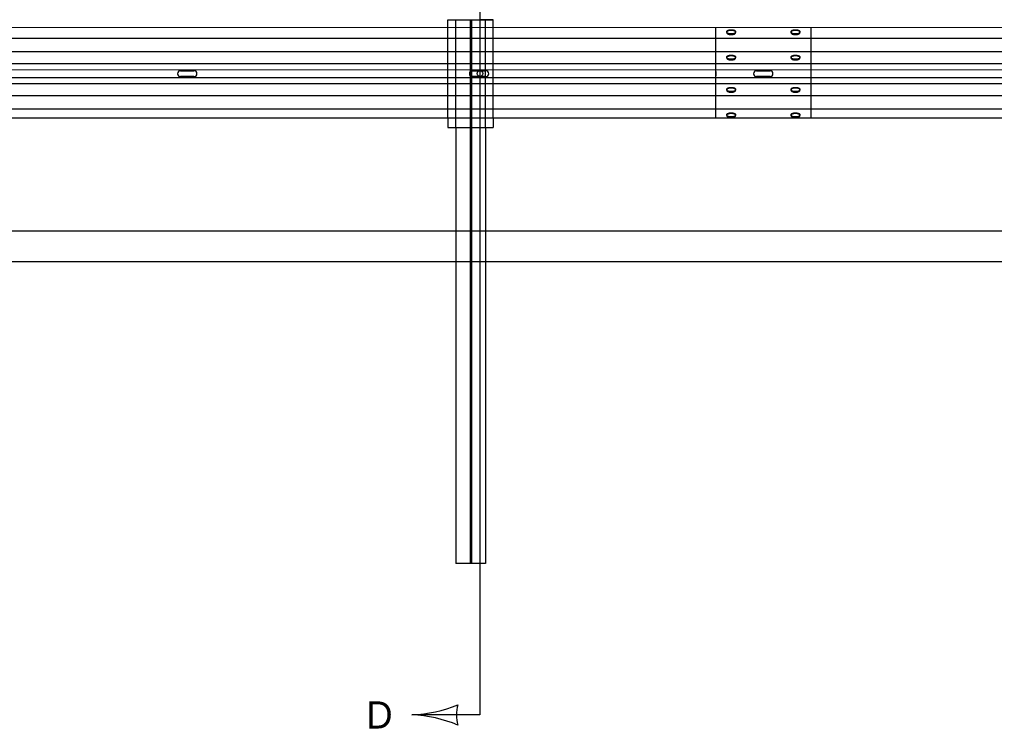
# Model space of a CAD drawing. Extents: x 49991 to 50160, y 49948 to 50051.
# Drawn here: x 50006.556 to 50008.707, y 49993.954 to 49995.519 of the extents above; entities that cross this region are included whole.
import ezdxf

# ---------------------------------------------------------------- set-up
doc = ezdxf.new("R2010")
doc.units = 0
for name, color, linetype in [('Level 1', 7, 'Continuous'), ('Level 2', 7, 'Continuous'), ('Level 3', 7, 'Continuous'), ('Level 4', 7, 'Continuous'), ('Level 6', 7, 'Continuous')]:
    doc.layers.add(name, color=color, linetype=linetype)

msp = doc.modelspace()

# ---------------------------------------------------------------- linework, layer by layer
at = {"layer": 'Level 1'}
for p, q in [((50007.5008, 49995.5184), (50007.6008, 49995.5184)), ((50007.5008, 49995.5018), (50007.5008, 49995.5184)), ((50007.5185, 49995.5184), (50007.5841, 49995.5184)), ((50007.6008, 49995.5184), (50007.5716, 49995.5184)), ((50007.6008, 49995.5018), (50007.6008, 49995.5184)), ((50004.3866, 49995.502), (50011.6716, 49995.5015)), ((50008.0917, 49995.3012), (50008.0917, 49995.5017)), ((50008.1159, 49995.4918), (50008.1159, 49995.4903)), ((50008.1238, 49995.4962), (50008.1277, 49995.4962)), ((50008.1238, 49995.4947), (50008.1238, 49995.4962)), ((50008.1277, 49995.4947), (50008.1238, 49995.4947)), ((50008.1277, 49995.4947), (50008.1277, 49995.4962)), ((50008.1356, 49995.4903), (50008.1356, 49995.4918)), ((50008.2577, 49995.4918), (50008.2577, 49995.4903)), ((50008.2655, 49995.4947), (50008.2655, 49995.4962)), ((50008.2655, 49995.4962), (50008.2695, 49995.4962)), ((50008.2695, 49995.4947), (50008.2655, 49995.4947)), ((50008.2695, 49995.4947), (50008.2695, 49995.4962)), ((50008.2774, 49995.4903), (50008.2774, 49995.4918)), ((50004.5497, 49995.4777), (50011.6716, 49995.4777)), ((50008.1277, 49995.4874), (50008.1238, 49995.4874)), ((50008.1238, 49995.4859), (50008.1238, 49995.4874)), ((50008.1238, 49995.4859), (50008.1277, 49995.4859)), ((50008.1277, 49995.4859), (50008.1277, 49995.4874)), ((50008.2695, 49995.4874), (50008.2655, 49995.4874)), ((50008.2655, 49995.4859), (50008.2655, 49995.4874)), ((50008.2655, 49995.4859), (50008.2695, 49995.4859)), ((50008.2695, 49995.4859), (50008.2695, 49995.4874)), ((50004.5497, 49995.4486), (50011.6716, 49995.448)), ((50008.1159, 49995.4357), (50008.1159, 49995.4342)), ((50008.1238, 49995.4401), (50008.1277, 49995.4401)), ((50008.1238, 49995.4401), (50008.1238, 49995.4387)), ((50008.1277, 49995.4387), (50008.1238, 49995.4387)), ((50008.1238, 49995.4313), (50008.1238, 49995.4298)), ((50008.1277, 49995.4313), (50008.1238, 49995.4313)), ((50008.1238, 49995.4298), (50008.1277, 49995.4298)), ((50008.1277, 49995.4401), (50008.1277, 49995.4387)), ((50008.1277, 49995.4313), (50008.1277, 49995.4298)), ((50008.1356, 49995.4342), (50008.1356, 49995.4357)), ((50008.2577, 49995.4357), (50008.2577, 49995.4342)), ((50008.2655, 49995.4401), (50008.2695, 49995.4401)), ((50008.2655, 49995.4401), (50008.2655, 49995.4387)), ((50008.2695, 49995.4387), (50008.2655, 49995.4387)), ((50008.2655, 49995.4313), (50008.2655, 49995.4298)), ((50008.2695, 49995.4313), (50008.2655, 49995.4313)), ((50008.2655, 49995.4298), (50008.2695, 49995.4298)), ((50008.2695, 49995.4401), (50008.2695, 49995.4387)), ((50008.2695, 49995.4313), (50008.2695, 49995.4298)), ((50008.2774, 49995.4342), (50008.2774, 49995.4357)), ((50004.5497, 49995.4215), (50011.6716, 49995.4225)), ((50005.0854, 49995.409), (50011.6716, 49995.4068)), ((50006.911, 49995.406), (50006.9406, 49995.406)), ((50007.5549, 49995.4059), (50007.5845, 49995.4059)), ((50008.0917, 49995.404), (50008.0917, 49995.4021)), ((50008.0917, 49995.4021), (50008.0917, 49995.4003)), ((50008.1819, 49995.4059), (50008.2114, 49995.4059)), ((50011.6716, 49995.3902), (50005.5897, 49995.3903)), ((50006.9406, 49995.3929), (50006.911, 49995.3929)), ((50007.5845, 49995.3928), (50007.5549, 49995.3928)), ((50008.0917, 49995.4003), (50008.0917, 49995.3984)), ((50008.0917, 49995.3984), (50008.0917, 49995.3966)), ((50008.0917, 49995.3966), (50008.0917, 49995.3948)), ((50008.2114, 49995.3928), (50008.1819, 49995.3928)), ((50011.6716, 49995.3773), (50005.5897, 49995.3773)), ((50008.1159, 49995.3645), (50008.1159, 49995.363)), ((50008.1238, 49995.3689), (50008.1277, 49995.3689)), ((50008.1238, 49995.3674), (50008.1238, 49995.3689)), ((50008.1277, 49995.3674), (50008.1238, 49995.3674)), ((50008.1277, 49995.3601), (50008.1238, 49995.3601)), ((50008.1238, 49995.3586), (50008.1238, 49995.3601)), ((50008.1277, 49995.3674), (50008.1277, 49995.3689)), ((50008.1277, 49995.3586), (50008.1277, 49995.3601)), ((50008.1356, 49995.363), (50008.1356, 49995.3645)), ((50008.2577, 49995.3645), (50008.2577, 49995.363)), ((50008.2655, 49995.3689), (50008.2695, 49995.3689)), ((50008.2655, 49995.3674), (50008.2655, 49995.3689)), ((50008.2695, 49995.3674), (50008.2655, 49995.3674)), ((50008.2695, 49995.3601), (50008.2655, 49995.3601)), ((50008.2655, 49995.3586), (50008.2655, 49995.3601)), ((50008.2695, 49995.3674), (50008.2695, 49995.3689)), ((50008.2695, 49995.3586), (50008.2695, 49995.3601)), ((50008.2774, 49995.363), (50008.2774, 49995.3645)), ((50011.6716, 49995.3504), (50005.5897, 49995.3504)), ((50008.1238, 49995.3586), (50008.1277, 49995.3586)), ((50008.2655, 49995.3586), (50008.2695, 49995.3586)), ((50011.6716, 49995.3214), (50005.5897, 49995.3214)), ((50011.6716, 49995.3012), (50005.5897, 49995.3012)), ((50007.5008, 49995.3012), (50007.5008, 49995.2809)), ((50007.6008, 49995.3012), (50007.6008, 49995.2809)), ((50008.1159, 49995.3084), (50008.1159, 49995.307)), ((50008.1238, 49995.3128), (50008.1277, 49995.3128)), ((50008.1238, 49995.3128), (50008.1238, 49995.3114)), ((50008.1277, 49995.3114), (50008.1238, 49995.3114)), ((50008.1238, 49995.304), (50008.1238, 49995.3025)), ((50008.1277, 49995.304), (50008.1238, 49995.304)), ((50008.1238, 49995.3025), (50008.1277, 49995.3025)), ((50008.1277, 49995.3128), (50008.1277, 49995.3114)), ((50008.1277, 49995.304), (50008.1277, 49995.3025)), ((50008.1356, 49995.307), (50008.1356, 49995.3084)), ((50008.2577, 49995.3084), (50008.2577, 49995.307)), ((50008.2655, 49995.3128), (50008.2695, 49995.3128)), ((50008.2655, 49995.3128), (50008.2655, 49995.3114)), ((50008.2695, 49995.3114), (50008.2655, 49995.3114)), ((50008.2655, 49995.304), (50008.2655, 49995.3025)), ((50008.2695, 49995.304), (50008.2655, 49995.304)), ((50008.2655, 49995.3025), (50008.2695, 49995.3025)), ((50008.2695, 49995.3128), (50008.2695, 49995.3114)), ((50008.2695, 49995.304), (50008.2695, 49995.3025)), ((50008.2774, 49995.307), (50008.2774, 49995.3084)), ((50007.5008, 49995.2809), (50007.6008, 49995.2809)), ((50007.5185, 49995.2809), (50007.5185, 49995.0517)), ((50007.5841, 49995.2809), (50007.5841, 49995.0517)), ((50011.6716, 49995.0515), (50000.8175, 49995.052)), ((49999.8238, 49994.9854), (50011.6716, 49994.9849))]:
    msp.add_line(p, q, dxfattribs=at)
for points in [[(50008.1238, 49995.4874), (50008.1224, 49995.4874), (50008.1211, 49995.4876), (50008.1199, 49995.488), (50008.1188, 49995.4884), (50008.1178, 49995.4889), (50008.117, 49995.4896), (50008.1164, 49995.4903), (50008.1161, 49995.491), (50008.1159, 49995.4918), (50008.1161, 49995.4925), (50008.1164, 49995.4933), (50008.117, 49995.494), (50008.1178, 49995.4946), (50008.1188, 49995.4952), (50008.1199, 49995.4956), (50008.1211, 49995.4959), (50008.1224, 49995.4961), (50008.1238, 49995.4962)], [(50008.116, 49995.4911), (50008.1159, 49995.4903), (50008.1161, 49995.4896), (50008.1164, 49995.4888), (50008.117, 49995.4881), (50008.1178, 49995.4875), (50008.1188, 49995.4869), (50008.1199, 49995.4865), (50008.1211, 49995.4862), (50008.1224, 49995.486), (50008.1238, 49995.4859)], [(50008.1238, 49995.4947), (50008.1224, 49995.4947), (50008.1211, 49995.4945), (50008.1199, 49995.4941), (50008.1188, 49995.4937), (50008.1178, 49995.4932), (50008.117, 49995.4925), (50008.1164, 49995.4918), (50008.1161, 49995.4911), (50008.116, 49995.4911)], [(50008.1277, 49995.4962), (50008.1291, 49995.4961), (50008.1304, 49995.4959), (50008.1317, 49995.4956), (50008.1328, 49995.4952), (50008.1338, 49995.4946), (50008.1346, 49995.494), (50008.1351, 49995.4933), (50008.1355, 49995.4925), (50008.1356, 49995.4918), (50008.1355, 49995.491), (50008.1351, 49995.4903), (50008.1346, 49995.4896), (50008.1338, 49995.4889), (50008.1328, 49995.4884), (50008.1317, 49995.488), (50008.1304, 49995.4876), (50008.1291, 49995.4874), (50008.1277, 49995.4874)], [(50008.1355, 49995.4911), (50008.1355, 49995.4911), (50008.1351, 49995.4918), (50008.1346, 49995.4925), (50008.1338, 49995.4932), (50008.1328, 49995.4937), (50008.1317, 49995.4941), (50008.1304, 49995.4945), (50008.1291, 49995.4947), (50008.1277, 49995.4947)], [(50008.1277, 49995.4859), (50008.1291, 49995.486), (50008.1304, 49995.4862), (50008.1317, 49995.4865), (50008.1328, 49995.4869), (50008.1338, 49995.4875), (50008.1346, 49995.4881), (50008.1351, 49995.4888), (50008.1355, 49995.4896), (50008.1356, 49995.4903), (50008.1355, 49995.4911)], [(50008.2655, 49995.4874), (50008.2642, 49995.4874), (50008.2629, 49995.4876), (50008.2616, 49995.488), (50008.2605, 49995.4884), (50008.2595, 49995.4889), (50008.2587, 49995.4896), (50008.2581, 49995.4903), (50008.2578, 49995.491), (50008.2577, 49995.4918), (50008.2578, 49995.4925), (50008.2581, 49995.4933), (50008.2587, 49995.494), (50008.2595, 49995.4946), (50008.2605, 49995.4952), (50008.2616, 49995.4956), (50008.2629, 49995.4959), (50008.2642, 49995.4961), (50008.2655, 49995.4962)], [(50008.2578, 49995.4911), (50008.2577, 49995.4903), (50008.2578, 49995.4896), (50008.2581, 49995.4888), (50008.2587, 49995.4881), (50008.2595, 49995.4875), (50008.2605, 49995.4869), (50008.2616, 49995.4865), (50008.2629, 49995.4862), (50008.2642, 49995.486), (50008.2655, 49995.4859)], [(50008.2655, 49995.4947), (50008.2642, 49995.4947), (50008.2629, 49995.4945), (50008.2616, 49995.4941), (50008.2605, 49995.4937), (50008.2595, 49995.4932), (50008.2587, 49995.4925), (50008.2581, 49995.4918), (50008.2578, 49995.4911), (50008.2578, 49995.4911)], [(50008.2695, 49995.4962), (50008.2708, 49995.4961), (50008.2722, 49995.4959), (50008.2734, 49995.4956), (50008.2745, 49995.4952), (50008.2755, 49995.4946), (50008.2763, 49995.494), (50008.2769, 49995.4933), (50008.2772, 49995.4925), (50008.2774, 49995.4918), (50008.2772, 49995.491), (50008.2769, 49995.4903), (50008.2763, 49995.4896), (50008.2755, 49995.4889), (50008.2745, 49995.4884), (50008.2734, 49995.488), (50008.2722, 49995.4876), (50008.2708, 49995.4874), (50008.2695, 49995.4874)], [(50008.2772, 49995.4911), (50008.2772, 49995.4911), (50008.2769, 49995.4918), (50008.2763, 49995.4925), (50008.2755, 49995.4932), (50008.2745, 49995.4937), (50008.2734, 49995.4941), (50008.2722, 49995.4945), (50008.2708, 49995.4947), (50008.2695, 49995.4947)], [(50008.2695, 49995.4859), (50008.2708, 49995.486), (50008.2722, 49995.4862), (50008.2734, 49995.4865), (50008.2745, 49995.4869), (50008.2755, 49995.4875), (50008.2763, 49995.4881), (50008.2769, 49995.4888), (50008.2772, 49995.4896), (50008.2774, 49995.4903), (50008.2772, 49995.4911)], [(50008.116, 49995.435), (50008.1159, 49995.4357), (50008.1161, 49995.4365), (50008.1164, 49995.4372), (50008.117, 49995.4379), (50008.1178, 49995.4385), (50008.1188, 49995.4391), (50008.1199, 49995.4395), (50008.1211, 49995.4398), (50008.1224, 49995.44), (50008.1238, 49995.4401)], [(50008.1238, 49995.4387), (50008.1224, 49995.4386), (50008.1211, 49995.4384), (50008.1199, 49995.4381), (50008.1188, 49995.4376), (50008.1178, 49995.4371), (50008.117, 49995.4365), (50008.1164, 49995.4358), (50008.1161, 49995.435), (50008.1159, 49995.4342), (50008.1161, 49995.4335), (50008.1164, 49995.4327), (50008.117, 49995.432), (50008.1178, 49995.4314), (50008.1188, 49995.4309), (50008.1199, 49995.4304), (50008.1211, 49995.4301), (50008.1224, 49995.4299), (50008.1238, 49995.4298)], [(50008.1238, 49995.4313), (50008.1224, 49995.4314), (50008.1211, 49995.4316), (50008.1199, 49995.4319), (50008.1188, 49995.4323), (50008.1178, 49995.4329), (50008.117, 49995.4335), (50008.1164, 49995.4342), (50008.1161, 49995.4349), (50008.116, 49995.435)], [(50008.1277, 49995.4401), (50008.1291, 49995.44), (50008.1304, 49995.4398), (50008.1317, 49995.4395), (50008.1328, 49995.4391), (50008.1338, 49995.4385), (50008.1346, 49995.4379), (50008.1351, 49995.4372), (50008.1355, 49995.4365), (50008.1356, 49995.4357), (50008.1355, 49995.435)], [(50008.1277, 49995.4298), (50008.1291, 49995.4299), (50008.1304, 49995.4301), (50008.1317, 49995.4304), (50008.1328, 49995.4309), (50008.1338, 49995.4314), (50008.1346, 49995.432), (50008.1351, 49995.4327), (50008.1355, 49995.4335), (50008.1356, 49995.4342), (50008.1355, 49995.435), (50008.1351, 49995.4358), (50008.1346, 49995.4365), (50008.1338, 49995.4371), (50008.1328, 49995.4376), (50008.1317, 49995.4381), (50008.1304, 49995.4384), (50008.1291, 49995.4386), (50008.1277, 49995.4387)], [(50008.1355, 49995.435), (50008.1355, 49995.4349), (50008.1351, 49995.4342), (50008.1346, 49995.4335), (50008.1338, 49995.4329), (50008.1328, 49995.4323), (50008.1317, 49995.4319), (50008.1304, 49995.4316), (50008.1291, 49995.4314), (50008.1277, 49995.4313)], [(50008.2578, 49995.435), (50008.2577, 49995.4357), (50008.2578, 49995.4365), (50008.2581, 49995.4372), (50008.2587, 49995.4379), (50008.2595, 49995.4385), (50008.2605, 49995.4391), (50008.2616, 49995.4395), (50008.2629, 49995.4398), (50008.2642, 49995.44), (50008.2655, 49995.4401)], [(50008.2655, 49995.4387), (50008.2642, 49995.4386), (50008.2629, 49995.4384), (50008.2616, 49995.4381), (50008.2605, 49995.4376), (50008.2595, 49995.4371), (50008.2587, 49995.4365), (50008.2581, 49995.4358), (50008.2578, 49995.435), (50008.2577, 49995.4342), (50008.2578, 49995.4335), (50008.2581, 49995.4327), (50008.2587, 49995.432), (50008.2595, 49995.4314), (50008.2605, 49995.4309), (50008.2616, 49995.4304), (50008.2629, 49995.4301), (50008.2642, 49995.4299), (50008.2655, 49995.4298)], [(50008.2655, 49995.4313), (50008.2642, 49995.4314), (50008.2629, 49995.4316), (50008.2616, 49995.4319), (50008.2605, 49995.4323), (50008.2595, 49995.4329), (50008.2587, 49995.4335), (50008.2581, 49995.4342), (50008.2578, 49995.4349), (50008.2578, 49995.435)], [(50008.2695, 49995.4401), (50008.2708, 49995.44), (50008.2722, 49995.4398), (50008.2734, 49995.4395), (50008.2745, 49995.4391), (50008.2755, 49995.4385), (50008.2763, 49995.4379), (50008.2769, 49995.4372), (50008.2772, 49995.4365), (50008.2774, 49995.4357), (50008.2772, 49995.435)], [(50008.2695, 49995.4298), (50008.2708, 49995.4299), (50008.2722, 49995.4301), (50008.2734, 49995.4304), (50008.2745, 49995.4309), (50008.2755, 49995.4314), (50008.2763, 49995.432), (50008.2769, 49995.4327), (50008.2772, 49995.4335), (50008.2774, 49995.4342), (50008.2772, 49995.435), (50008.2769, 49995.4358), (50008.2763, 49995.4365), (50008.2755, 49995.4371), (50008.2745, 49995.4376), (50008.2734, 49995.4381), (50008.2722, 49995.4384), (50008.2708, 49995.4386), (50008.2695, 49995.4387)], [(50008.2772, 49995.435), (50008.2772, 49995.4349), (50008.2769, 49995.4342), (50008.2763, 49995.4335), (50008.2755, 49995.4329), (50008.2745, 49995.4323), (50008.2734, 49995.4319), (50008.2722, 49995.4316), (50008.2708, 49995.4314), (50008.2695, 49995.4313)], [(50008.1238, 49995.3601), (50008.1224, 49995.3601), (50008.1211, 49995.3603), (50008.1199, 49995.3607), (50008.1188, 49995.3611), (50008.1178, 49995.3616), (50008.117, 49995.3623), (50008.1164, 49995.363), (50008.1161, 49995.3637), (50008.1159, 49995.3645), (50008.1161, 49995.3652), (50008.1164, 49995.366), (50008.117, 49995.3667), (50008.1178, 49995.3673), (50008.1188, 49995.3679), (50008.1199, 49995.3683), (50008.1211, 49995.3686), (50008.1224, 49995.3688), (50008.1238, 49995.3689)], [(50008.116, 49995.3638), (50008.1159, 49995.363), (50008.1161, 49995.3623), (50008.1164, 49995.3615), (50008.117, 49995.3608), (50008.1178, 49995.3602), (50008.1188, 49995.3597), (50008.1199, 49995.3592), (50008.1211, 49995.3589), (50008.1224, 49995.3587), (50008.1238, 49995.3586)], [(50008.1238, 49995.3674), (50008.1224, 49995.3674), (50008.1211, 49995.3672), (50008.1199, 49995.3668), (50008.1188, 49995.3664), (50008.1178, 49995.3659), (50008.117, 49995.3652), (50008.1164, 49995.3645), (50008.1161, 49995.3638), (50008.116, 49995.3638)], [(50008.1277, 49995.3689), (50008.1291, 49995.3688), (50008.1304, 49995.3686), (50008.1317, 49995.3683), (50008.1328, 49995.3679), (50008.1338, 49995.3673), (50008.1346, 49995.3667), (50008.1351, 49995.366), (50008.1355, 49995.3652), (50008.1356, 49995.3645), (50008.1355, 49995.3637), (50008.1351, 49995.363), (50008.1346, 49995.3623), (50008.1338, 49995.3616), (50008.1328, 49995.3611), (50008.1317, 49995.3607), (50008.1304, 49995.3603), (50008.1291, 49995.3601), (50008.1277, 49995.3601)], [(50008.1355, 49995.3638), (50008.1355, 49995.3638), (50008.1351, 49995.3645), (50008.1346, 49995.3652), (50008.1338, 49995.3659), (50008.1328, 49995.3664), (50008.1317, 49995.3668), (50008.1304, 49995.3672), (50008.1291, 49995.3674), (50008.1277, 49995.3674)], [(50008.1277, 49995.3586), (50008.1291, 49995.3587), (50008.1304, 49995.3589), (50008.1317, 49995.3592), (50008.1328, 49995.3597), (50008.1338, 49995.3602), (50008.1346, 49995.3608), (50008.1351, 49995.3615), (50008.1355, 49995.3623), (50008.1356, 49995.363), (50008.1355, 49995.3638)], [(50008.2655, 49995.3601), (50008.2642, 49995.3601), (50008.2629, 49995.3603), (50008.2616, 49995.3607), (50008.2605, 49995.3611), (50008.2595, 49995.3616), (50008.2587, 49995.3623), (50008.2581, 49995.363), (50008.2578, 49995.3637), (50008.2577, 49995.3645), (50008.2578, 49995.3652), (50008.2581, 49995.366), (50008.2587, 49995.3667), (50008.2595, 49995.3673), (50008.2605, 49995.3679), (50008.2616, 49995.3683), (50008.2629, 49995.3686), (50008.2642, 49995.3688), (50008.2655, 49995.3689)], [(50008.2578, 49995.3638), (50008.2577, 49995.363), (50008.2578, 49995.3623), (50008.2581, 49995.3615), (50008.2587, 49995.3608), (50008.2595, 49995.3602), (50008.2605, 49995.3597), (50008.2616, 49995.3592), (50008.2629, 49995.3589), (50008.2642, 49995.3587), (50008.2655, 49995.3586)], [(50008.2655, 49995.3674), (50008.2642, 49995.3674), (50008.2629, 49995.3672), (50008.2616, 49995.3668), (50008.2605, 49995.3664), (50008.2595, 49995.3659), (50008.2587, 49995.3652), (50008.2581, 49995.3645), (50008.2578, 49995.3638), (50008.2578, 49995.3638)], [(50008.2695, 49995.3689), (50008.2708, 49995.3688), (50008.2722, 49995.3686), (50008.2734, 49995.3683), (50008.2745, 49995.3679), (50008.2755, 49995.3673), (50008.2763, 49995.3667), (50008.2769, 49995.366), (50008.2772, 49995.3652), (50008.2774, 49995.3645), (50008.2772, 49995.3637), (50008.2769, 49995.363), (50008.2763, 49995.3623), (50008.2755, 49995.3616), (50008.2745, 49995.3611), (50008.2734, 49995.3607), (50008.2722, 49995.3603), (50008.2708, 49995.3601), (50008.2695, 49995.3601)], [(50008.2772, 49995.3638), (50008.2772, 49995.3638), (50008.2769, 49995.3645), (50008.2763, 49995.3652), (50008.2755, 49995.3659), (50008.2745, 49995.3664), (50008.2734, 49995.3668), (50008.2722, 49995.3672), (50008.2708, 49995.3674), (50008.2695, 49995.3674)], [(50008.2695, 49995.3586), (50008.2708, 49995.3587), (50008.2722, 49995.3589), (50008.2734, 49995.3592), (50008.2745, 49995.3597), (50008.2755, 49995.3602), (50008.2763, 49995.3608), (50008.2769, 49995.3615), (50008.2772, 49995.3623), (50008.2774, 49995.363), (50008.2772, 49995.3638)], [(50008.116, 49995.3077), (50008.1159, 49995.3084), (50008.1161, 49995.3092), (50008.1164, 49995.3099), (50008.117, 49995.3106), (50008.1178, 49995.3112), (50008.1188, 49995.3118), (50008.1199, 49995.3122), (50008.1211, 49995.3125), (50008.1224, 49995.3127), (50008.1238, 49995.3128)], [(50008.1238, 49995.3114), (50008.1224, 49995.3113), (50008.1211, 49995.3111), (50008.1199, 49995.3108), (50008.1188, 49995.3103), (50008.1178, 49995.3098), (50008.117, 49995.3092), (50008.1164, 49995.3085), (50008.1161, 49995.3077), (50008.1159, 49995.307), (50008.1161, 49995.3062), (50008.1164, 49995.3054), (50008.117, 49995.3047), (50008.1178, 49995.3041), (50008.1188, 49995.3036), (50008.1199, 49995.3031), (50008.1211, 49995.3028), (50008.1224, 49995.3026), (50008.1238, 49995.3025)], [(50008.1238, 49995.304), (50008.1224, 49995.3041), (50008.1211, 49995.3043), (50008.1199, 49995.3046), (50008.1188, 49995.305), (50008.1178, 49995.3056), (50008.117, 49995.3062), (50008.1164, 49995.3069), (50008.1161, 49995.3076), (50008.116, 49995.3077)], [(50008.1277, 49995.3128), (50008.1291, 49995.3127), (50008.1304, 49995.3125), (50008.1317, 49995.3122), (50008.1328, 49995.3118), (50008.1338, 49995.3112), (50008.1346, 49995.3106), (50008.1351, 49995.3099), (50008.1355, 49995.3092), (50008.1356, 49995.3084), (50008.1355, 49995.3077)], [(50008.1277, 49995.3025), (50008.1291, 49995.3026), (50008.1304, 49995.3028), (50008.1317, 49995.3031), (50008.1328, 49995.3036), (50008.1338, 49995.3041), (50008.1346, 49995.3047), (50008.1351, 49995.3054), (50008.1355, 49995.3062), (50008.1356, 49995.307), (50008.1355, 49995.3077), (50008.1351, 49995.3085), (50008.1346, 49995.3092), (50008.1338, 49995.3098), (50008.1328, 49995.3103), (50008.1317, 49995.3108), (50008.1304, 49995.3111), (50008.1291, 49995.3113), (50008.1277, 49995.3114)], [(50008.1355, 49995.3077), (50008.1355, 49995.3076), (50008.1351, 49995.3069), (50008.1346, 49995.3062), (50008.1338, 49995.3056), (50008.1328, 49995.305), (50008.1317, 49995.3046), (50008.1304, 49995.3043), (50008.1291, 49995.3041), (50008.1277, 49995.304)], [(50008.2578, 49995.3077), (50008.2577, 49995.3084), (50008.2578, 49995.3092), (50008.2581, 49995.3099), (50008.2587, 49995.3106), (50008.2595, 49995.3112), (50008.2605, 49995.3118), (50008.2616, 49995.3122), (50008.2629, 49995.3125), (50008.2642, 49995.3127), (50008.2655, 49995.3128)], [(50008.2655, 49995.3114), (50008.2642, 49995.3113), (50008.2629, 49995.3111), (50008.2616, 49995.3108), (50008.2605, 49995.3103), (50008.2595, 49995.3098), (50008.2587, 49995.3092), (50008.2581, 49995.3085), (50008.2578, 49995.3077), (50008.2577, 49995.307), (50008.2578, 49995.3062), (50008.2581, 49995.3054), (50008.2587, 49995.3047), (50008.2595, 49995.3041), (50008.2605, 49995.3036), (50008.2616, 49995.3031), (50008.2629, 49995.3028), (50008.2642, 49995.3026), (50008.2655, 49995.3025)], [(50008.2655, 49995.304), (50008.2642, 49995.3041), (50008.2629, 49995.3043), (50008.2616, 49995.3046), (50008.2605, 49995.305), (50008.2595, 49995.3056), (50008.2587, 49995.3062), (50008.2581, 49995.3069), (50008.2578, 49995.3076), (50008.2578, 49995.3077)], [(50008.2695, 49995.3128), (50008.2708, 49995.3127), (50008.2722, 49995.3125), (50008.2734, 49995.3122), (50008.2745, 49995.3118), (50008.2755, 49995.3112), (50008.2763, 49995.3106), (50008.2769, 49995.3099), (50008.2772, 49995.3092), (50008.2774, 49995.3084), (50008.2772, 49995.3077)], [(50008.2695, 49995.3025), (50008.2708, 49995.3026), (50008.2722, 49995.3028), (50008.2734, 49995.3031), (50008.2745, 49995.3036), (50008.2755, 49995.3041), (50008.2763, 49995.3047), (50008.2769, 49995.3054), (50008.2772, 49995.3062), (50008.2774, 49995.307), (50008.2772, 49995.3077), (50008.2769, 49995.3085), (50008.2763, 49995.3092), (50008.2755, 49995.3098), (50008.2745, 49995.3103), (50008.2734, 49995.3108), (50008.2722, 49995.3111), (50008.2708, 49995.3113), (50008.2695, 49995.3114)], [(50008.2772, 49995.3077), (50008.2772, 49995.3076), (50008.2769, 49995.3069), (50008.2763, 49995.3062), (50008.2755, 49995.3056), (50008.2745, 49995.305), (50008.2734, 49995.3046), (50008.2722, 49995.3043), (50008.2708, 49995.3041), (50008.2695, 49995.304)]]:
    msp.add_lwpolyline(points, dxfattribs=at)
msp.add_circle((50007.5716, 49995.3996), 0.00625, dxfattribs=at)
for centre, start, end in [((50006.911, 49995.3994), 90, 270), ((50006.9406, 49995.3994), 270, 90), ((50007.5549, 49995.3994), 90, 270), ((50007.5845, 49995.3994), 270, 90), ((50008.1819, 49995.3994), 90, 270), ((50008.2114, 49995.3994), 270, 90)]:
    msp.add_arc(centre, 0.00656, start, end, dxfattribs=at)
at = {"layer": 'Level 3'}
for centre, radius, start, end in [((50007.4063, 49994.2941), 0.3107, 272.8273, 292.0772), ((50007.5926, 49993.9838), 0.073, 162.1388, 197.8612), ((50007.4094, 49993.6876), 0.2964, 67.456, 87.6395)]:
    msp.add_arc(centre, radius, start, end, dxfattribs=at)
at = {"layer": 'Level 4'}
for p, q in [((50007.5185, 49995.2809), (50007.5185, 49995.5184)), ((50007.5499, 49995.5184), (50007.5499, 49994.3184)), ((50007.5527, 49995.5184), (50007.5527, 49994.3184)), ((50007.5841, 49995.2809), (50007.5841, 49995.5184)), ((50007.5008, 49995.3012), (50007.5008, 49995.5018)), ((50007.6008, 49995.3012), (50007.6008, 49995.5018)), ((50008.3016, 49995.5017), (50008.3016, 49995.4988)), ((50008.3016, 49995.4988), (50008.3016, 49995.4976)), ((50008.3016, 49995.4976), (50008.3016, 49995.4775)), ((50008.3016, 49995.4775), (50008.3016, 49995.4485)), ((50008.3016, 49995.4485), (50008.3016, 49995.4216)), ((50008.3016, 49995.4216), (50008.3016, 49995.4086)), ((50008.3016, 49995.4086), (50008.3016, 49995.3902)), ((50008.3016, 49995.3902), (50008.3016, 49995.3771)), ((50008.3016, 49995.3771), (50008.3016, 49995.3502)), ((50008.3016, 49995.3502), (50008.3016, 49995.3212)), ((50008.3016, 49995.3212), (50008.3016, 49995.3012)), ((50007.5185, 49995.0517), (50007.5185, 49994.3184)), ((50007.5841, 49995.0517), (50007.5841, 49994.3184)), ((50007.5841, 49994.3184), (50007.5185, 49994.3184))]:
    msp.add_line(p, q, dxfattribs=at)
at = {"layer": 'Level 6'}
for p, q in [((50007.5716, 49995.8225), (50007.5716, 49993.9838)), ((50007.5716, 49993.9838), (50007.4216, 49993.9838))]:
    msp.add_line(p, q, dxfattribs=at)

# ---------------------------------------------------------------- texts
at = {"layer": 'Level 2'}
msp.add_text('D', height=0.06, dxfattribs=at).set_placement((50007.3209, 49993.9538))

doc.saveas('drawing.dxf')
